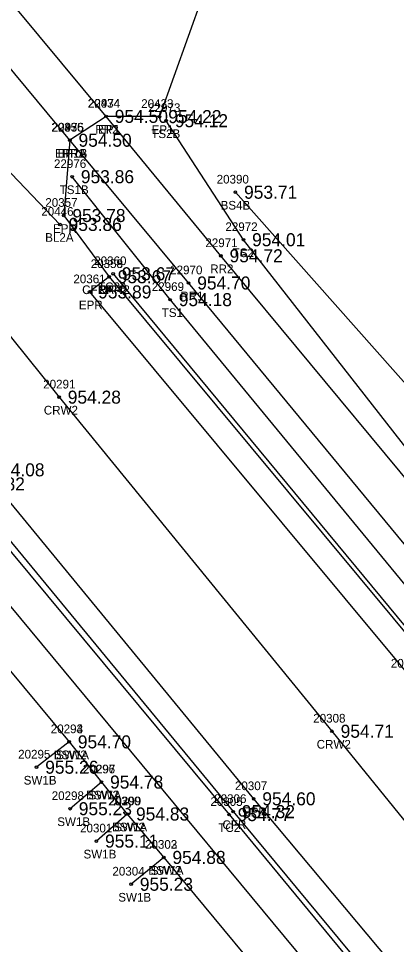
# Model space of a CAD drawing. Extents: x 1576181 to 1577685, y 1099396 to 1101490.
# Drawn here: x 1576437.8 to 1576481.4, y 1099504.3 to 1099611 of the extents above; entities that cross this region are included whole.
import ezdxf

# ---------------------------------------------------------------- set-up
doc = ezdxf.new("R2010")
doc.units = 0
for name, color, linetype in [('RD_DTM_BkLn1', 7, 'Continuous'), ('RD_DTM_BkLn2', 7, 'Continuous'), ('RD_DTM_BkLn_txCode', 7, 'Continuous'), ('RD_EX_Conc', 7, 'Continuous'), ('RD_EX_Conc_txCode', 7, 'Continuous'), ('RD_EX_RailRoad', 7, 'Continuous'), ('RD_EX_RailRoad_txCode', 7, 'Continuous'), ('RD_EX_Road', 7, 'Continuous'), ('RD_EX_Road_txCode', 7, 'Continuous'), ('RD_EX_TX_Conc_ELEV', 7, 'Continuous'), ('RD_EX_TX_Misc_ELEV', 7, 'Continuous'), ('RD_EX_TX_RailRoad_ELEV', 7, 'Continuous'), ('RD_EX_TX_Road_ELEV', 7, 'Continuous'), ('RD_HC_Survey_ELEV', 7, 'Continuous'), ('RD_HC_Survey_txCode', 7, 'Continuous'), ('RD_SMD_Locator', 7, 'Continuous')]:
    doc.layers.add(name, color=color, linetype=linetype)

msp = doc.modelspace()

# ---------------------------------------------------------------- linework, layer by layer
at = {"layer": 'RD_DTM_BkLn1'}
for points in [[(1576442.61, 1099587.26), (1576417.82, 1099613.19), (1576402.2, 1099632.12), (1576392.54, 1099647.43)], [(1576411.06, 1099606.41), (1576442.51, 1099567.37), (1576473.98, 1099528.89), (1576505.72, 1099489.81), (1576537.1, 1099451.4), (1576568.87, 1099412.8)]]:
    msp.add_lwpolyline(points, dxfattribs=at)
at = {"layer": 'RD_DTM_BkLn2'}
for points in [[(1576591.01, 1099431.27), (1576559.41, 1099470.13), (1576528.39, 1099507.67), (1576493.55, 1099547.49), (1576463.77, 1099585.5), (1576454.86, 1099599.21)], [(1576583.18, 1099425.1), (1576550.35, 1099462.76), (1576519.49, 1099500.89), (1576486.17, 1099541.19), (1576455.31, 1099578.6), (1576444.02, 1099592.76)], [(1576596.97, 1099435.73), (1576565.79, 1099473.1), (1576527.76, 1099518.95), (1576499.74, 1099549.43), (1576462.84, 1099590.97)], [(1576448.74, 1099581.58), (1576485.59, 1099537.16), (1576516.95, 1099499.35), (1576549.15, 1099460.28), (1576581.13, 1099421.81)], [(1576411.94, 1099579.95), (1576414.49, 1099576.96), (1576418.07, 1099572.26), (1576420.73, 1099569.37), (1576424.53, 1099564.75), (1576430.75, 1099556.96), (1576462.11, 1099519.29), (1576494.91, 1099479.63), (1576525.82, 1099442.2), (1576557.4, 1099404.07)]]:
    msp.add_lwpolyline(points, dxfattribs=at)
at = {"layer": 'RD_EX_Conc'}
for p, q in [((1576443.67, 1099527.67), (1576439.91, 1099524.75)), ((1576447.39, 1099523.04), (1576443.78, 1099519.97)), ((1576450.38, 1099519.36), (1576446.81, 1099516.24)), ((1576454.58, 1099514.36), (1576450.82, 1099511.27))]:
    msp.add_line(p, q, dxfattribs=at)
for points in [[(1576396.55, 1099574.21), (1576400.94, 1099578.26), (1576405.4, 1099581.45), (1576408.35, 1099582.39), (1576411.1, 1099581.54), (1576412.48, 1099580.16), (1576412.48, 1099580.16), (1576431.43, 1099557.37), (1576462.58, 1099519.63), (1576495.36, 1099480.14), (1576526.3, 1099442.62), (1576558.03, 1099404.43)], [(1576448.28, 1099581.24), (1576485.22, 1099536.89), (1576516.55, 1099498.95), (1576548.71, 1099459.94), (1576580.64, 1099421.45)], [(1576424.53, 1099564.75), (1576421.54, 1099562.11), (1576427.77, 1099554.24), (1576491.4, 1099477.63), (1576522.92, 1099439.59), (1576554.46, 1099401.18)], [(1576417.79, 1099558.83), (1576419.81, 1099556.41), (1576422.78, 1099552.79), (1576443.67, 1099527.67), (1576447.39, 1099523.04), (1576450.38, 1099519.36), (1576454.58, 1099514.36), (1576470.78, 1099494.84), (1576474, 1099490.99), (1576488.02, 1099473.93), (1576497.44, 1099462.54), (1576500.63, 1099458.76), (1576516.67, 1099439.27), (1576520.69, 1099434.46), (1576523.68, 1099430.77), (1576527.93, 1099425.88), (1576541.66, 1099409.22), (1576544.52, 1099405.7), (1576551.21, 1099397.69)]]:
    msp.add_lwpolyline(points, dxfattribs=at)
at = {"layer": 'RD_EX_RailRoad'}
for points in [[(1576588.64, 1099429.74), (1576556.82, 1099468.27), (1576525.53, 1099505.93), (1576492.19, 1099546.33), (1576461.17, 1099583.65), (1576447.93, 1099599.71), (1576411.91, 1099642.96), (1576369.31, 1099694.21), (1576336.53, 1099733.7), (1576300.55, 1099777.04), (1576258.58, 1099827.59)], [(1576584.91, 1099426.47), (1576552.99, 1099465.14), (1576521.86, 1099502.63), (1576488.35, 1099543.2), (1576457.44, 1099580.52), (1576443.75, 1099596.96), (1576408.06, 1099639.92), (1576365.56, 1099691.12), (1576332.82, 1099730.47), (1576296.82, 1099773.87), (1576254.94, 1099824.3)]]:
    msp.add_lwpolyline(points, dxfattribs=at)
at = {"layer": 'RD_EX_Road'}
for points in [[(1576459.06, 1099613.56), (1576454.1, 1099599.68), (1576447.93, 1099599.71), (1576443.75, 1099596.96)], [(1576443.75, 1099596.96), (1576443.04, 1099588.29), (1576448.28, 1099581.24), (1576446.02, 1099579.49), (1576482.91, 1099535.22), (1576514.34, 1099496.99), (1576546.16, 1099458.39), (1576578.5, 1099419.58)], [(1576365.09, 1099547.1), (1576400.46, 1099578.87), (1576404.99, 1099582.28), (1576408.27, 1099583.27), (1576411.47, 1099582.29), (1576413.12, 1099580.85), (1576414.82, 1099582.11), (1576433.7, 1099559), (1576464.95, 1099521.11), (1576497.8, 1099481.91), (1576528.73, 1099444.46), (1576560.01, 1099406.61)]]:
    msp.add_lwpolyline(points, dxfattribs=at)
at = {"layer": 'RD_SMD_Locator'}
for centre in [(1576447.93, 1099599.71), (1576447.93, 1099599.71), (1576454.1, 1099599.68), (1576454.86, 1099599.21), (1576443.75, 1099596.96), (1576443.75, 1099596.96), (1576443.75, 1099596.96), (1576444.02, 1099592.76), (1576462.84, 1099590.97), (1576443.04, 1099588.29), (1576442.61, 1099587.26), (1576463.77, 1099585.5), (1576461.17, 1099583.65), (1576448.74, 1099581.58), (1576448.28, 1099581.24), (1576448.28, 1099581.24), (1576457.44, 1099580.52), (1576446.02, 1099579.49), (1576455.31, 1099578.6), (1576442.51, 1099567.37), (1576473.98, 1099528.89), (1576443.67, 1099527.67), (1576443.67, 1099527.67), (1576439.91, 1099524.75), (1576447.39, 1099523.04), (1576447.39, 1099523.04), (1576464.95, 1099521.11), (1576443.78, 1099519.97), (1576462.58, 1099519.63), (1576450.38, 1099519.36), (1576450.38, 1099519.36), (1576462.11, 1099519.29), (1576446.81, 1099516.24), (1576454.58, 1099514.36), (1576454.58, 1099514.36), (1576450.82, 1099511.27)]:
    msp.add_circle(centre, 0.15, dxfattribs=at)

# ---------------------------------------------------------------- texts
at = {"layer": 'RD_DTM_BkLn_txCode'}
for s, p in [('22973', (1576452.78, 1099600.21)), ('TS2B', (1576453.14, 1099597.21)), ('22976', (1576441.92, 1099593.76)), ('20390', (1576460.68, 1099591.97)), ('TS1B', (1576442.58, 1099590.76)), ('20446', (1576440.46, 1099588.26)), ('BS4B', (1576461.14, 1099588.97)), ('22972', (1576461.69, 1099586.5)), ('BL2A', (1576440.91, 1099585.26)), ('TS2', (1576462.53, 1099583.5)), ('22969', (1576453.2, 1099579.6)), ('TS1', (1576454.35, 1099576.6))]:
    msp.add_text(s, height=1, dxfattribs=at).set_placement(p)
at = {"layer": 'RD_EX_Conc_txCode'}
for s, p in [('20359', (1576446.16, 1099582.24)), ('20360', (1576446.56, 1099582.58)), ('TC2A', (1576447.01, 1099579.58)), ('CFRA 42', (1576445.17, 1099579.24)), ('20293', (1576441.55, 1099528.67)), ('20294', (1576441.55, 1099528.67)), ('20295', (1576437.79, 1099525.75)), ('BSW2', (1576441.91, 1099525.67)), ('SW1A', (1576442.17, 1099525.67)), ('20296', (1576445.25, 1099524.04)), ('20297', (1576445.28, 1099524.04)), ('SW1B', (1576438.43, 1099522.75)), ('20298', (1576441.66, 1099520.97)), ('BSW2', (1576445.63, 1099521.04)), ('SW1A', (1576445.9, 1099521.04)), ('20300', (1576448.18, 1099520.36)), ('20299', (1576448.26, 1099520.36)), ('20305', (1576459.96, 1099520.29)), ('20306', (1576460.4, 1099520.63)), ('SW1B', (1576442.3, 1099517.97)), ('20301', (1576444.93, 1099517.24)), ('BSW2', (1576448.62, 1099517.36)), ('SW1A', (1576448.88, 1099517.36)), ('TC2', (1576460.87, 1099517.29)), ('CFR', (1576461.35, 1099517.63)), ('20302', (1576452.42, 1099515.36)), ('20303', (1576452.42, 1099515.36)), ('SW1B', (1576445.33, 1099514.24)), ('BSW2', (1576452.81, 1099512.36)), ('SW1A', (1576453.08, 1099512.36)), ('20304', (1576448.66, 1099512.27)), ('SW1B', (1576449.34, 1099509.27))]:
    msp.add_text(s, height=1, dxfattribs=at).set_placement(p)
at = {"layer": 'RD_EX_RailRoad_txCode'}
for s, p in [('22974', (1576445.85, 1099600.71)), ('22975', (1576441.67, 1099597.96)), ('RR2', (1576446.7, 1099597.71)), ('RR1', (1576442.8, 1099594.96)), ('22971', (1576459.38, 1099584.65)), ('RR2', (1576459.94, 1099581.65)), ('22970', (1576455.32, 1099581.52)), ('RR1', (1576456.49, 1099578.52))]:
    msp.add_text(s, height=1, dxfattribs=at).set_placement(p)
at = {"layer": 'RD_EX_Road_txCode'}
for s, p in [('20434', (1576445.81, 1099600.71)), ('20433', (1576451.98, 1099600.68)), ('20356', (1576441.61, 1099597.96)), ('20435', (1576441.63, 1099597.96)), ('EP1', (1576447.01, 1099597.71)), ('EP1', (1576453.18, 1099597.68)), ('EPRA', (1576442.03, 1099594.96)), ('EP1B', (1576442.35, 1099594.96)), ('20357', (1576440.92, 1099589.29)), ('EPR', (1576441.81, 1099586.29)), ('20358', (1576446.16, 1099582.24)), ('20361', (1576444.16, 1099580.49)), ('EPR', (1576447.05, 1099579.24)), ('EPR', (1576444.79, 1099577.49)), ('20362', (1576480.77, 1099536.22)), ('20307', (1576462.79, 1099522.11)), ('EPR', (1576463.72, 1099519.11))]:
    msp.add_text(s, height=1, dxfattribs=at).set_placement(p)
at = {"layer": 'RD_EX_TX_Conc_ELEV'}
for s, p in [('953.67', (1576449.28, 1099580.49)), ('953.67', (1576449.74, 1099580.83)), ('953.82', (1576432.43, 1099556.62)), ('954.70', (1576444.67, 1099526.92)), ('954.70', (1576444.67, 1099526.92)), ('955.26', (1576440.91, 1099524)), ('954.78', (1576448.39, 1099522.29)), ('954.78', (1576448.39, 1099522.29)), ('955.23', (1576444.78, 1099519.22)), ('954.83', (1576451.38, 1099518.61)), ('954.83', (1576451.38, 1099518.61)), ('954.77', (1576463.11, 1099518.54)), ('954.32', (1576463.58, 1099518.88)), ('955.11', (1576447.81, 1099515.49)), ('954.88', (1576455.58, 1099513.61)), ('954.88', (1576455.58, 1099513.61)), ('955.23', (1576451.82, 1099510.52))]:
    msp.add_text(s, height=1.5, dxfattribs=at).set_placement(p)
at = {"layer": 'RD_EX_TX_Misc_ELEV'}
for s, p in [('954.12', (1576455.86, 1099598.46)), ('953.86', (1576445.02, 1099592.01)), ('953.71', (1576463.84, 1099590.22)), ('953.86', (1576443.61, 1099586.51)), ('954.01', (1576464.77, 1099584.75)), ('954.18', (1576456.31, 1099577.85))]:
    msp.add_text(s, height=1.5, dxfattribs=at).set_placement(p)
at = {"layer": 'RD_EX_TX_RailRoad_ELEV'}
for s, p in [('954.50', (1576448.93, 1099598.96)), ('954.50', (1576444.75, 1099596.21)), ('954.72', (1576462.17, 1099582.9)), ('954.70', (1576458.44, 1099579.77))]:
    msp.add_text(s, height=1.5, dxfattribs=at).set_placement(p)
at = {"layer": 'RD_EX_TX_Road_ELEV'}
for s, p in [('954.50', (1576448.93, 1099598.96)), ('954.22', (1576455.1, 1099598.93)), ('954.50', (1576444.75, 1099596.21)), ('954.50', (1576444.75, 1099596.21)), ('953.78', (1576444.04, 1099587.54)), ('953.67', (1576449.28, 1099580.49)), ('953.89', (1576447.02, 1099578.74)), ('954.08', (1576434.7, 1099558.25)), ('954.60', (1576465.95, 1099520.36))]:
    msp.add_text(s, height=1.5, dxfattribs=at).set_placement(p)
at = {"layer": 'RD_HC_Survey_ELEV'}
for s, p in [('954.28', (1576443.51, 1099566.62)), ('954.71', (1576474.98, 1099528.14))]:
    msp.add_text(s, height=1.5, dxfattribs=at).set_placement(p)
at = {"layer": 'RD_HC_Survey_txCode'}
for s, p in [('20291', (1576440.68, 1099568.37)), ('CRW2', (1576440.75, 1099565.37)), ('20308', (1576471.82, 1099529.89)), ('CRW2', (1576472.22, 1099526.89))]:
    msp.add_text(s, height=1, dxfattribs=at).set_placement(p)

doc.saveas('drawing.dxf')
